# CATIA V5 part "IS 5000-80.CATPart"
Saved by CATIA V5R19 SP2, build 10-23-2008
Part number: IS 5000-80
Bounding box of the stored display mesh (mm): x -59.975 to 59.975, y -59.975 to 59.975, z 0 to 300
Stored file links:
  C:\Users\Bora\Desktop\3D Katı model\IS serisi\IS 5000\IS 5000-80.CATPart
  C:\Program Files\Dassault Systemes\B19\intel_a\reffiles\standard\MetricThickPitch.txt
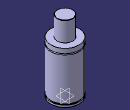
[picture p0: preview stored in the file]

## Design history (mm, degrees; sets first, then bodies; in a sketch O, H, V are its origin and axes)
Body1 (main body)
  Sketch1 on yz-plane, origin (0, 0, 0), H (0, 1, 0), V (0, 0, 1)
    point P1 (60, 197)
    point P4 (60, 192)
    point P7 (32.5, 299)
    point P9 (32.5, 299)
    point P13 (60, 197)
    point P14 (60, 192)
    line L1 (60, 197) -> (60, 217)
    line L2 (60, 13) -> (60, 192)
    line L3 (56, 13) -> (56, 8)
    arc A1 centre (31.5, 299) radius 1 from (32.5, 299) to (31.5, 300) ccw
    line L4 (32.5, 299) -> (32.5, 217)
    line L5 (60, 0) -> (60, 8)
    arc A2 centre (60, 194.5) radius 2.5 from (60, 197) to (60, 192) ccw
    line L6 (31.5, 300) -> (0, 300)
    point P15 (0, 300)
    line L7 (32.5, 217) -> (60, 217)
    line L8 (0, 0) -> (60, 0)
    line L9 (56, 13) -> (60, 13)
    line L10 (56, 8) -> (60, 8)
    coincidence: P15 V, P1 P13, P4 P14, P7 P9
    tangency: L6 A1
    horizontal: L7 H, L8 H, L9 H, L10 H
  Shaft1: profile Sketch1, axis Sketch1.V, angle 360
  Sketch2 on face of Shaft1 from Sketch1.L8, origin (0, 0, 0), H (1, 0, 0), V (0, -1, 0)
    point P1 (40, 0)
    distance P1 V = 40
  Hole1: placed by Sketch2, at (40, 0, 0) direction (0, 0, 1), diameter 8.376, depth 16, threaded "M10", thread diameter 10, thread depth 16, pitch 1.5
  CircPattern1: of Hole1, instances 4, angular step 90, axis from xy-plane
